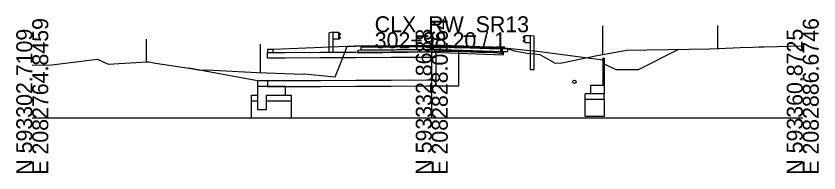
# Model space of a CAD drawing. Extents: x -26 to 2138, y -10 to 4518.
# Drawn here: x 997.2 to 1137.8, y -9.7 to 17.8 of the extents above; entities that cross this region are included whole.
import ezdxf

# ---------------------------------------------------------------- set-up
doc = ezdxf.new("R2010")
doc.units = 0
for name, color, linetype in [('DR_P_Erosion_Control', 7, 'Continuous'), ('GK_Cells', 7, 'Continuous'), ('MD_P_Surface_Aggregate_Base', 7, 'Continuous'), ('MD_P_Surface_Asphalt_Concrete_Base', 7, 'Continuous'), ('MD_P_Surface_Asphalt_Concrete_Intermediate_Course', 7, 'Continuous'), ('MD_P_Surface_Asphalt_Concrete_Surface_Course', 7, 'Continuous'), ('MD_P_Surface_Non-Reinforced_Concrete_Pavement', 7, 'Continuous'), ('MD_X_Asphalt_Pavement', 7, 'Continuous'), ('PV_P_EOP', 7, 'Continuous'), ('RD_P_Cells', 7, 'Continuous'), ('RW_P_Esmt_SH', 7, 'Continuous'), ('RW_X_Esmt_SH', 7, 'Continuous'), ('SC_Scratch1', 7, 'Continuous'), ('UT_X_Water', 7, 'Continuous'), ('XS_P_Excavation_Limits', 7, 'Continuous'), ('XS_P_Finished_Grade', 7, 'Continuous'), ('XS_X_Ground_Line', 7, 'Continuous')]:
    doc.layers.add(name, color=color, linetype=linetype)

msp = doc.modelspace()

# ---------------------------------------------------------------- linework, layer by layer
at = {"layer": 'DR_P_Erosion_Control'}
for p, q in [((1039.47, 6.46), (1027.43, 8.69)), ((1041.19, 6.46), (1039.47, 6.46)), ((1039.47, 6.46), (1039.47, 5.46))]:
    msp.add_line(p, q, dxfattribs=at)
at = {"layer": 'GK_Cells'}
for p, q in [((1070, 0), (1070, 15)), ((1000, 0), (1070, 0)), ((1070, 0), (1135, 0))]:
    msp.add_line(p, q, dxfattribs=at)
at = {"layer": 'MD_P_Surface_Aggregate_Base'}
for points in [[(1070, 11.98), (1070, 11.48), (1057.12, 11.35), (1057.12, 11.85), (1070, 11.98)], [(1070, 11.98), (1070, 11.48), (1082.59, 11.05), (1082.59, 11.55), (1070, 11.98)]]:
    msp.add_lwpolyline(points, dxfattribs=at)
at = {"layer": 'MD_P_Surface_Asphalt_Concrete_Base'}
for points in [[(1070, 12.48), (1070, 11.98), (1057.62, 11.86), (1057.62, 12.36), (1070, 12.48)], [(1070, 12.48), (1070, 11.98), (1082.09, 11.57), (1082.09, 12.07), (1081.75, 12.08), (1070, 12.48)]]:
    msp.add_lwpolyline(points, dxfattribs=at)
at = {"layer": 'MD_P_Surface_Asphalt_Concrete_Intermediate_Course'}
for points in [[(1070, 12.63), (1070, 12.48), (1057.95, 12.36), (1057.95, 12.51), (1070, 12.63)], [(1070, 12.63), (1070, 12.48), (1081.75, 12.08), (1081.75, 12.23), (1070, 12.63)]]:
    msp.add_lwpolyline(points, dxfattribs=at)
at = {"layer": 'MD_P_Surface_Asphalt_Concrete_Surface_Course'}
for points in [[(1070, 12.73), (1070, 12.63), (1057.95, 12.51), (1057.95, 12.61), (1070, 12.73)], [(1070, 12.73), (1070, 12.63), (1081.75, 12.23), (1081.75, 12.33), (1070, 12.73)]]:
    msp.add_lwpolyline(points, dxfattribs=at)
at = {"layer": 'MD_P_Surface_Non-Reinforced_Concrete_Pavement'}
for points in [[(1041.19, 11.46), (1042.22, 11.46), (1042.22, 11.96), (1041.19, 11.96), (1041.19, 11.46)], [(1070.7, 11.59), (1070.7, 10.59), (1069.1, 10.58), (1062.91, 10.55), (1056.72, 10.53), (1050.52, 10.5), (1044.33, 10.47), (1041.19, 10.46), (1041.19, 11.46), (1044.33, 11.47), (1050.52, 11.5), (1056.72, 11.53), (1062.91, 11.55), (1069.1, 11.58), (1070.7, 11.59)], [(1074.73, 5.61), (1074.73, 11.61), (1071.54, 11.59), (1070.7, 11.59), (1070.7, 5.59), (1071.54, 5.59), (1074.73, 5.61)], [(1100.23, 5.72), (1100.03, 5.72), (1100.03, 10.48), (1100.23, 10.47), (1100.23, 5.72)], [(1070.7, 5.59), (1070.7, 6.59), (1069.1, 6.58), (1062.91, 6.55), (1056.72, 6.53), (1050.52, 6.5), (1046.54, 6.48), (1044.33, 6.47), (1041.19, 6.46), (1041.19, 5.46), (1044.33, 5.47), (1050.52, 5.5), (1056.72, 5.53), (1062.91, 5.55), (1069.1, 5.58), (1070.7, 5.59)], [(1100.23, 4.67), (1100.23, 4.22), (1098.95, 4.22), (1097.88, 4.22), (1097.88, 5.1), (1097.88, 5.72), (1100.23, 5.72), (1100.23, 4.67)], [(1040.4, 5.46), (1039.47, 5.46), (1039.47, 3.77), (1039.47, 1.46), (1039.94, 1.46), (1041.02, 1.46), (1041.02, 1.56), (1041.02, 3.96), (1041.09, 3.96), (1041.17, 3.96), (1044.37, 3.96), (1044.37, 5.15), (1044.37, 5.46), (1041.17, 5.46), (1040.4, 5.46)]]:
    msp.add_lwpolyline(points, dxfattribs=at)
at = {"layer": 'MD_X_Asphalt_Pavement'}
msp.add_lwpolyline([(1071.44, 12.69), (1071.44, 11.73), (1075.62, 11.59), (1078, 11.5), (1080.8, 11.42), (1081.45, 11.37), (1081.95, 11.33), (1082.41, 11.32), (1082.41, 12.28), (1081.95, 12.29), (1081.45, 12.33), (1080.8, 12.38), (1078, 12.46), (1075.62, 12.54), (1071.44, 12.69)], dxfattribs=at)
at = {"layer": 'PV_P_EOP'}
msp.add_line((1057.95, 12.61), (1042.22, 11.96), dxfattribs=at)
at = {"layer": 'RD_P_Cells'}
for p, q in [((1052.1, 14.91), (1052.05, 14.88)), ((1052.05, 11.51), (1052.05, 14.88)), ((1052.64, 14.99), (1052.1, 14.91)), ((1052.72, 14.95), (1052.64, 14.99)), ((1053.72, 14.95), (1052.72, 14.95)), ((1052.72, 11.51), (1052.72, 14.95)), ((1053.72, 13.76), (1053.72, 14.95)), ((1053.81, 14.85), (1053.72, 14.86)), ((1053.73, 14.35), (1053.73, 14.4)), ((1053.73, 14.31), (1053.73, 14.35)), ((1053.76, 14.46), (1053.97, 14.61)), ((1053.97, 14.1), (1053.76, 14.24)), ((1053.97, 14.73), (1053.81, 14.85)), ((1086.03, 14.19), (1086.19, 14.31)), ((1086.19, 14.31), (1086.28, 14.32)), ((1086.28, 13.22), (1086.28, 14.41)), ((1086.28, 14.41), (1087.28, 14.41)), ((1087.28, 14.41), (1087.36, 14.45)), ((1087.28, 8.45), (1087.28, 14.41)), ((1087.36, 14.45), (1087.9, 14.37)), ((1087.9, 14.37), (1087.95, 14.34)), ((1087.95, 8.45), (1087.95, 14.34)), ((1053.72, 13.76), (1052.72, 13.76)), ((1053.72, 13.84), (1053.81, 13.86)), ((1053.81, 13.86), (1053.97, 13.97)), ((1086.24, 13.92), (1086.03, 14.07)), ((1086.03, 13.56), (1086.24, 13.7)), ((1086.19, 13.32), (1086.03, 13.43)), ((1086.28, 13.3), (1086.19, 13.32)), ((1086.27, 13.81), (1086.27, 13.86)), ((1086.27, 13.77), (1086.27, 13.81)), ((1086.28, 13.22), (1087.28, 13.22)), ((1087.28, 8.45), (1087.95, 8.45))]:
    msp.add_line(p, q, dxfattribs=at)
for points in [[(1053.74, 14.41), (1053.74, 14.29), (1053.73, 14.29), (1053.73, 14.41)], [(1053.74, 14.38), (1053.74, 14.32), (1053.76, 14.32), (1053.76, 14.38)], [(1086.26, 13.84), (1086.26, 13.78), (1086.24, 13.78), (1086.24, 13.84)], [(1086.26, 13.87), (1086.26, 13.75), (1086.27, 13.75), (1086.27, 13.87)]]:
    msp.add_lwpolyline(points, close=True, dxfattribs=at)
for centre, start, end in [((1053.81, 14.4), 124.962, 180), ((1053.81, 14.31), 180, 235.038), ((1053.92, 14.67), 304.962, 54.7677), ((1053.92, 14.03), 304.962, 54.7677), ((1086.08, 14.13), 125.2323, 235.038), ((1086.08, 13.5), 125.2323, 235.038), ((1086.19, 13.86), 0, 55.038), ((1086.19, 13.77), 304.962, 0)]:
    msp.add_arc(centre, 0.0781, start, end, dxfattribs=at)
at = {"layer": 'RW_P_Esmt_SH'}
for p, q in [((1120.13, 12.17), (1120.13, 16.17)), ((1020, 9.78), (1020, 13.78))]:
    msp.add_line(p, q, dxfattribs=at)
at = {"layer": 'RW_X_Esmt_SH'}
for p, q in [((1100, 11.11), (1100, 16.11)), ((1040, 7.89), (1040, 12.89))]:
    msp.add_line(p, q, dxfattribs=at)
at = {"layer": 'SC_Scratch1'}
for p, q in [((1057.95, 12.61), (1070, 12.73)), ((1070, 12.73), (1081.75, 12.33)), ((1057.95, 12.51), (1070, 12.63)), ((1057.95, 12.61), (1057.95, 12.36)), ((1057.95, 12.36), (1070, 12.48)), ((1070, 12.63), (1081.75, 12.23)), ((1070, 12.48), (1082.09, 12.07)), ((1074.73, 11.61), (1083.25, 11.64)), ((1081.75, 12.33), (1081.75, 12.08)), ((1081.75, 12.33), (1083.25, 12.18)), ((1082.09, 12.07), (1082.09, 11.64)), ((1083.25, 12.18), (1083.25, 11.64))]:
    msp.add_line(p, q, dxfattribs=at)
at = {"layer": 'UT_X_Water'}
msp.add_circle((1095, 6.31), 0.3, dxfattribs=at)
at = {"layer": 'XS_P_Excavation_Limits'}
for p, q in [((1038.44, -0.04), (1038.44, 3.96)), ((1038.44, 3.96), (1039.47, 3.96)), ((1038.44, 2.96), (1039.47, 2.96)), ((1041.02, 2.96), (1045.4, 2.96)), ((1044.37, 3.96), (1045.4, 3.96)), ((1045.4, -0.04), (1045.4, 3.96)), ((1096.85, 0.22), (1096.85, 4.22)), ((1097.88, 4.22), (1096.85, 4.22)), ((1100.23, 3.22), (1096.85, 3.22)), ((1100.23, 3.22), (1100.23, 4.22)), ((1100.23, 3.22), (1100.23, 0.22)), ((1100.23, 0.22), (1096.85, 0.22)), ((1038.44, -0.04), (1045.4, -0.04))]:
    msp.add_line(p, q, dxfattribs=at)
at = {"layer": 'XS_P_Finished_Grade'}
for p, q in [((1083.25, 12.18), (1088.95, 11.61)), ((1088.95, 11.61), (1100.03, 10.14)), ((1106.23, 8.47), (1113.31, 12.01)), ((1100.23, 9.47), (1102.23, 8.47)), ((1102.23, 8.47), (1106.23, 8.47))]:
    msp.add_line(p, q, dxfattribs=at)
at = {"layer": 'XS_X_Ground_Line'}
msp.add_lwpolyline([(1000, 9.25), (1003.41, 9.27), (1011.4, 10.28), (1013.3, 9.39), (1020.1, 9.79), (1020.18, 9.78), (1020.25, 9.78), (1020.32, 9.78), (1020.43, 9.78), (1021.61, 9.59), (1027.43, 8.69), (1029.45, 8.37), (1030.56, 8.39), (1039.39, 7.91), (1047.51, 7.66), (1047.67, 7.69), (1052.43, 7.26), (1053.09, 7.17), (1053.81, 9.04), (1055.17, 12.49), (1056.62, 12.53), (1059.66, 12.64), (1067.44, 12.7), (1070.14, 12.73), (1078, 12.46), (1080.8, 12.38), (1081.95, 12.29), (1082.41, 12.28), (1082.59, 12.17), (1083.45, 12.08), (1084.46, 11.74), (1086.72, 11.3), (1088.92, 11.11), (1091.61, 9.58), (1091.64, 9.55), (1092.81, 9.61), (1093.08, 9.71), (1098.7, 10.88), (1104.1, 11.83), (1118.65, 12.11), (1120.29, 12.17), (1124.06, 12.3), (1126.31, 12.38), (1127.32, 12.41), (1128.26, 12.43), (1135, 12.64)], dxfattribs=at)

# ---------------------------------------------------------------- texts
msp.add_text('-', height=0.0001).set_placement((1000, 0))
at = {"layer": 'GK_Cells'}
for s, p in [('E 2082764.8459', (1002.8, -10)), ('E 2082828.0164', (1072.8, -10)), ('E 2082886.6746', (1137.8, -10)), ('N 593302.7109', (1000, -10)), ('N 593332.8688', (1070, -10)), ('N 593360.8725', (1135, -10))]:
    msp.add_text(s, height=2.8, rotation=90, dxfattribs=at).set_placement(p)
for s, p in [('CLX_RW_SR13', (1060, 15)), ('302+98.20 / 1', (1060, 12.2))]:
    msp.add_text(s, height=2.8, dxfattribs=at).set_placement(p)

doc.saveas('drawing.dxf')
